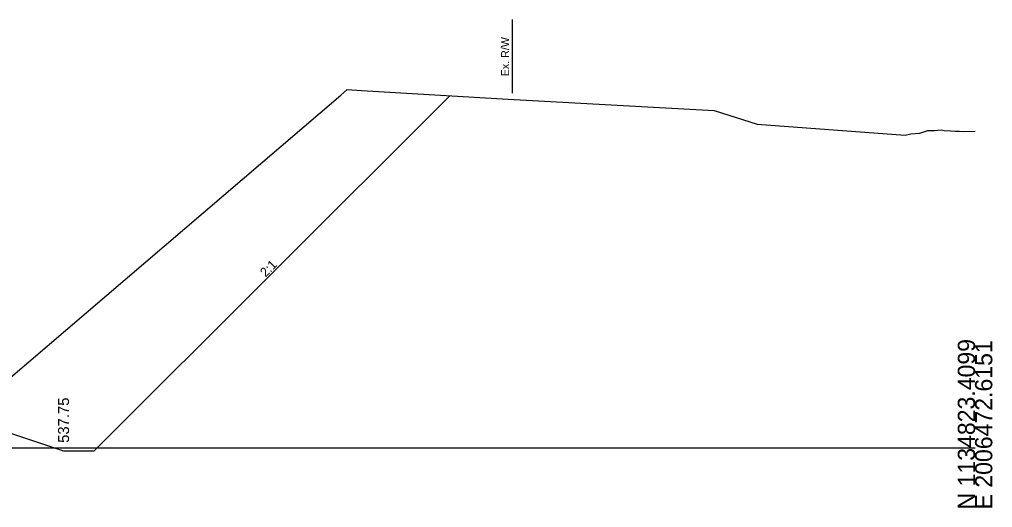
# Model space of a CAD drawing. Extents: x -201 to 2007062, y -213 to 1139737.
# Drawn here: x 1344.8 to 1502.8, y 990.3 to 1069.6 of the extents above; entities that cross this region are included whole.
import ezdxf

# ---------------------------------------------------------------- set-up
doc = ezdxf.new("R2010")
doc.units = 0
for name, color, linetype in [('RD_GPK_XS_Cell', 7, 'Continuous'), ('RD_Sketch1', 7, 'Continuous'), ('RD_XS_ExGround', 7, 'Continuous'), ('RD_XS_ExRW', 7, 'Continuous'), ('RD_XS_TieSlope', 7, 'Continuous'), ('RD_XS_TX_Ditch', 7, 'Continuous'), ('RD_XS_TX_Slope', 7, 'Continuous')]:
    doc.layers.add(name, color=color, linetype=linetype)

msp = doc.modelspace()

# ---------------------------------------------------------------- linework, layer by layer
at = {"layer": 'RD_GPK_XS_Cell'}
msp.add_line((1250, 1000), (1500, 1000), dxfattribs=at)
at = {"layer": 'RD_XS_ExGround'}
msp.add_lwpolyline([(1343.03, 1011.12), (1397.05, 1057.33), (1398.06, 1058.22), (1400.4, 1058.08), (1424.22, 1056.65), (1457.66, 1054.79), (1464.62, 1052.6), (1488.67, 1050.81), (1489.56, 1051), (1491.06, 1051.14), (1492, 1051.45), (1492.35, 1051.56), (1493.39, 1051.55), (1494.5, 1051.67), (1495.01, 1051.57), (1496.02, 1051.51), (1496.79, 1051.44), (1497.48, 1051.46), (1498.1, 1051.38), (1500, 1051.46)], dxfattribs=at)
at = {"layer": 'RD_XS_ExRW'}
msp.add_line((1424.85, 1069.61), (1424.85, 1057.61), dxfattribs=at)
at = {"layer": 'RD_XS_TieSlope'}
msp.add_lwpolyline([(1328, 1007.5), (1352, 999.5), (1357, 999.5), (1414.72, 1057.22)], dxfattribs=at)

# ---------------------------------------------------------------- texts
at = {"layer": 'RD_GPK_XS_Cell'}
for s, p in [('N 1134823.4099', (1500, 990)), ('E 2006472.6151', (1502.8, 990))]:
    msp.add_text(s, height=2.8, rotation=90, dxfattribs=at).set_placement(p)
at = {"layer": 'RD_Sketch1'}
for s, p in [('Exterior Boundary', (1414.16, 1057.17)), ('LOC_C', (1414.49, 1057.17)), ('Cut_Ditch', (1351.7, 999.45)), ('Cut_Ditch1', (1356.67, 999.45))]:
    msp.add_text(s, height=0.05, dxfattribs=at).set_placement(p)
at = {"layer": 'RD_XS_ExRW'}
msp.add_text('Ex. R/W ', height=1.3, rotation=90, dxfattribs=at).set_placement((1424.35, 1060.37))
at = {"layer": 'RD_XS_TX_Ditch'}
msp.add_text('537.75', height=1.8, rotation=90, dxfattribs=at).set_placement((1352.9, 1000.82))
at = {"layer": 'RD_XS_TX_Slope'}
msp.add_text('2:1', height=1.5, rotation=45, dxfattribs=at).set_placement((1384.81, 1027.67))

doc.saveas('drawing.dxf')
